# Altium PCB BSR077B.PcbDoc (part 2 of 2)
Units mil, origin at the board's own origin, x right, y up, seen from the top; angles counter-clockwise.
Board outline 2900 x 1600 mil, 4 copper layers (Top Layer, Signal Layer 1, Signal Layer 2, Bottom Layer), stack 40 mil thick; 58 components, 11 nets, 111 pads, 62 vias.
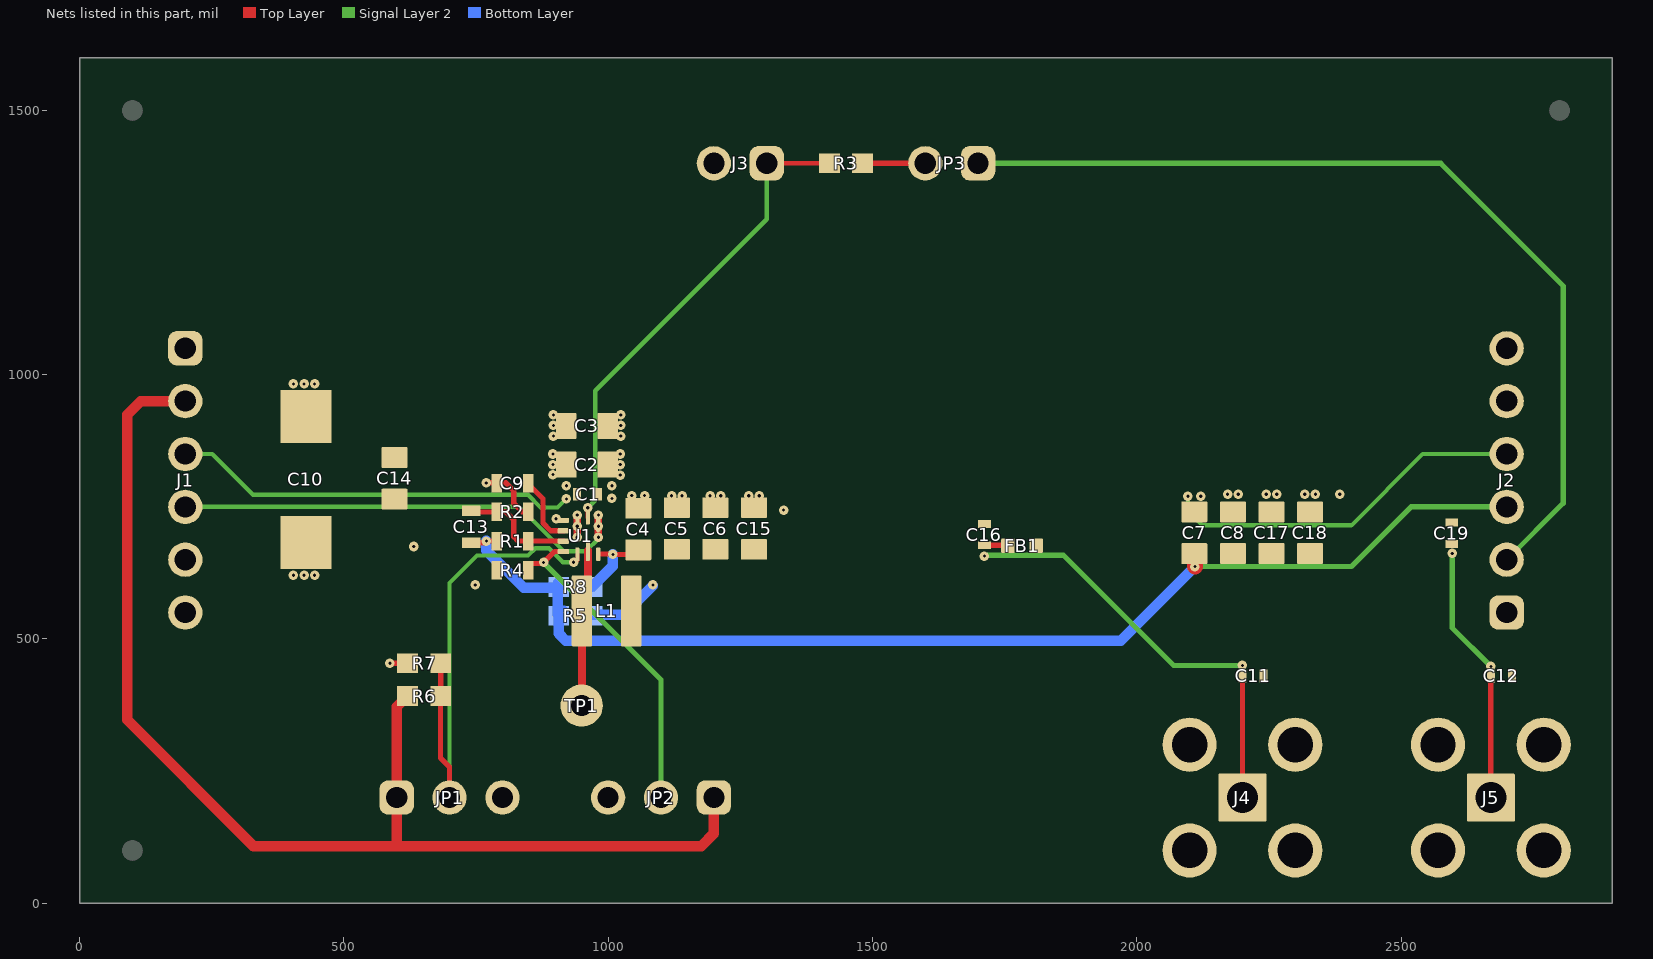
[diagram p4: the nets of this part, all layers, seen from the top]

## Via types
v1: diameter 18, hole 6, Top Layer to Bottom Layer, tented both sides, 53 vias
v2: diameter 18, hole 6.1, Top Layer to Bottom Layer, tented both sides, 9 vias

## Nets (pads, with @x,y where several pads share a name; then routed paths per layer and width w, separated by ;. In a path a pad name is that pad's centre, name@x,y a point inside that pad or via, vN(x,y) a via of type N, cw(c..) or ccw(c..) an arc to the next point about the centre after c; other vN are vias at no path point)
EN: JP1.2 R6.2 R7.2 U1.1 | length 992.7
  Top Layer w8: v2(934.59,645.35) 937.59,645.35 941.9,649.66 U1.1@941.9,660.45
  Top Layer w10: JP1.2@683,213 JP1.2@702,194 ; R7.2@683.5,454 R6.2@683.5,392 683,391.5 683,275 700,258 JP1.2@700,200
  Signal Layer 2 w8: JP1.2@700,200 700,606 752,658 848.35,658 862,671.65 887.9,671.65 914.2,645.35 v2(934.59,645.35) ; JP1.2@702,194 JP1.2@702,200
FB: C13.2 R1.1 R2.2 U1.9 | length 228.6
  Top Layer w10: C13.2@729.59,740.35 789,740.35 R2.2@791.59,740.35 ; R2.2@790.59,741.35 805.59,741.35 821.59,725.35 821.59,693.41 829.65,685.35 851.59,685.35 U1.9@915.33,685.06
GND: C1.2 C2.1 C3.1 C4.2 C5.2 C6.2 C7.2 C8.2 C9.2 C10.2 C11.2 C12.2 C14.1 C15.2 C16.2 C17.2 C18.2 C19.2 J1.4 J1.5 J1.6 J2.4 J2.5 J2.6 J3.2 J4.2 J4.3 J4.4 J4.5 J5.2 J5.3 J5.4 J5.5 JP1.3 JP2.3 R2.1 R4.1 R7.1 U1.4 U1.7 | length 1719.6
  Top Layer w10: v1(587,454) R7.1@620.5,454 ; v1(769.35,795.35) C9.2@791.59,795.35 ; C9.2@792.59,795.35 806.59,795.35 821.59,780.35 821.59,756.35 837.59,740.35 R2.1@851.59,740.35
  Top Layer w15: U1.4@981.27,734.03 U1.4@981.27,722.46 981.27,692.66 v2(981.59,692.35)
  Signal Layer 2 w8: J1.4@200,750 832,750 915.78,666.22 958.22,666.22 981.59,689.59 v2(981.59,692.35) ; v1(2097,770) 2097,743 2125,715 2406,715 2541,850 J2.4@2700,850
  other v1: 748.59,602.35 404.65,620.59 424.65,620.59 444.65,620.59 632.15,675 1332,744 1007,766 2121,770 1044.7,771.2 1069,771.2 1119.9,771 1139.9,771 1192.9,771 1212.9,771 1265.9,771 1285.9,771 2172,774 2192,774 2245,774 2265,774 2318,774 2338,774 2384,774 1007,790 1023,810 1023,830 1023,850 1024,884 1024,904 1024,924
  other v2: 981.59,713.35 901.59,727.35 981.59,734.35
NetJP3_2: JP3.2 R3.2 | length 125
  Top Layer w10: R3.2@1475,1400 R3.2@1481.5,1400 JP3.2@1600,1400
PG: J3.1 R3.1 U1.5 | length 937.6
  Top Layer w8: U1.5@961.59,729.35 v2(961.59,748.35) ; J3.1@1300,1400 R3.1@1418.5,1400 R3.1@1425,1400
  Signal Layer 2 w8: v2@963.35,748.35 v2(961.59,748.35) 975.62,762.38 975.62,969.62 1300,1294 J3.1@1300,1400
SCONF: JP2.2 R4.2 U1.10 | length 605.5
  Top Layer w10: R4.2@856,643 876,643 v1(878,645) 898.37,665.37 U1.10@915.33,665.37
  Signal Layer 2 w10: v1(878,645) 1100,423 JP2.2@1100,200
SS: C9.1 U1.8 | length 131.1
  Top Layer w10: C9.1@851.59,795.35 851.59,790.35 876.59,765.35 876.59,719.35 891.19,704.74 U1.8@915.33,704.74
SW: L1.1 TP1.1 U1.2 | length 294.9
  Top Layer w15: L1.1@948,541 L1.1@949,542 ; TP1.1@950,374 950.35,374.35 L1.1@950.35,553 ; L1.1@961.59,553 U1.2@961.59,667.34
VIN: C1.1 C2.2 C3.2 C10.1 C14.2 J1.1 J1.2 J1.3 JP1.1 JP2.1 R6.1 U1.6 | length 3102.8
  Top Layer w15: v2(941.59,692.35) v2(941.59,734.35)
  Top Layer w20: J1.2@200,950 116,950 90,924 90,347 329,108 599,108 ; JP1.1@602,194 JP1.1@611,203 ; R6.1@620.5,392 600,371.5 JP1.1@600,200 600,109 599,108 ; JP2.1@1200,200 1200,132 1176,108 599,108
  Signal Layer 2 w8: J1.3@200,850 251,850 328.13,772.87 848.13,772.87 872,749 904.24,749 920.24,765 v1(921,765) v1@922,765
  other v1: 921,790 895.42,811 895.42,830 895.42,850 896.42,884 896.42,904 896.42,924 404.65,982.59 424.65,982.59 444.65,982.59
  other v2: 941.59,713.35
VOUT: C4.1 C5.1 C6.1 C11.1 C15.1 C16.1 FB1.1 J4.1 L1.2 R5.2 R8.1 U1.3 | length 1161.5
  Top Layer w10: U1.3@983,661 1010,661 v1(1009,660) C4.1@1050,660 ; C16.1@1712,677.29 1755.43,677.29 FB1.1@1756.43,676.29 ; J4.1@2200,200 C11.1@2200,430 v1(2200,450)
  Signal Layer 2 w10: v1(1712,656.75) 1713.71,658.46 1861.54,658.46 2070,450 v1(2200,450)
  Bottom Layer w10: R5.2@967.5,546 R5.2@969.5,548 ; v1@1084.6,600.6 v1(1084.6,602.35)
  Bottom Layer w20: R5.2@967.5,546 1030,546 v1@1084.6,600.6 ; R8.1@969.5,598.5 1009,638 v1(1009,660)
VOUT_FILT: C7.1 C8.1 C12.1 C13.1 C17.1 C18.1 C19.1 FB1.2 J2.1 J2.2 J2.3 J5.1 JP3.1 R1.2 R5.1 R8.2 | length 4560.9
  Top Layer w10: C13.1@740.59,682.35 766.59,682.35 v1(769.59,685.35) R1.2@791.59,685.35 ; J5.1@2670,200 C12.1@2670,430 v1(2670,448) ; J2.1@2700,551 J2.1@2705,546
  Top Layer w30: C7.1@2109,661.63 2110,660.63 v1(2110,637)
  Signal Layer 2 w10: JP3.1@1700,1400 2575,1400 2807,1168 2807,757 J2.2@2700,650 ; v1(2110,637) 2406.25,637 2519.25,750 J2.3@2700,750 ; v1(2597,662) 2597,521 v1(2670,448)
  Bottom Layer w10: R8.2@896.5,597 904.5,605 915,605 R8.2@915.26,598.88 ; R5.1@906.5,544 904.5,546 R5.1@917,558.5
  Bottom Layer w20: v1(769.59,685.35) 769.59,667.41 840,597 R8.2@896.5,597 ; R5.1@904.5,546 R8.2@904.5,605 ; R5.1@906.5,544 906.5,510.5 920,497 1970,497 v1(2110,637)
pads on no net: FID1.1 FID2.1 FID3.1 FID4.1 FID5.1 FID6.1 LBL1.0 SH-JP1.0 SH-JP2.0 SH-JP3.0

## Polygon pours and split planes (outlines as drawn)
GND on Bottom Layer "BOTTOM_LAYER_GND_P084" (solid, remove dead copper, pour order 84): 0,1600 2900,1600 2900,0 0,0
VOUT on Top Layer "TOP_LAYER_VOUT_P090" (solid, remove dead copper, pour order 90): 1344,480 1773,480 1773,693.96 1030,694.03 1030,620 1010,620 1000,610 1000,479.89 1229,479.89 1229,480
GND on Top Layer "TOP_LAYER_GND_P096" (solid, remove dead copper, pour order 96): 0,1600 2900,1600 2900,0 0,0
VOUT_FILT on Top Layer "TOP_LAYER_VOUT_FILT_P094" (solid, remove dead copper, pour order 94): 1783,480 2118,480 2720,480 2750,510 2750,694.17 1783,694.17 1783,644
VIN on Top Layer "TOP_LAYER_VIN_P086" (solid, remove dead copper, pour order 86): 930,680 930,720.71 826.77,823 130,823 130,1120 853,1120 955,1018 955,680
GND on Signal Layer 1 "SIGNAL_LAYER_1_GND_P078" (solid, remove dead copper, pour order 78): 0,1600 2900,1600 2900,0 0,0
GND on Signal Layer 2 "SIGNAL_LAYER_2_GND_P098" (solid, remove dead copper, pour order 98): -0.1,1597.05 2899.9,1597.05 2899.9,-2.95 -0.1,-2.95
VIN on Signal Layer 2 "SIGNAL_LAYER_2_VIN_P080" (solid, remove dead copper, pour order 80): 930,680 930,731.05 872.53,788 335,788 223.47,899.53 130,899.53 130,1118 853,1118 960,1011 960,680

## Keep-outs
Keep-Out Layer:
  text ".Layer_Name" at 577,-858.49 h60

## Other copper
Top Layer:
  pour cut-out: 2699.88,890.06 cw(c2699.88,849.64) 2740.3,849.64 cw(c2699.88,849.64) 2699.88,809.22 cw(c2699.88,849.64) 2659.47,849.64 cw(c2699.88,849.64)
  pour cut-out: 199.88,890.06 cw(c199.88,849.64) 240.3,849.64 cw(c199.88,849.64) 199.88,809.22 cw(c199.88,849.64) 159.47,849.64 cw(c199.88,849.64)
  pour cut-out: 199.88,790.06 cw(c199.88,749.64) 240.3,749.64 cw(c199.88,749.64) 199.88,709.22 cw(c199.88,749.64) 159.47,749.64 cw(c199.88,749.64)
  pour cut-out: 1391.59,352.35
  pour cut-out: 2450,499.46
  pour cut-out: 1450,534
  text ".Layer_Name" at 577,-858.49 h60
Signal Layer 1:
  pour cut-out: 2699.82,809.73 cw(c2699.82,850.14) 2659.4,850.14 cw(c2699.82,850.14) 2699.82,890.56 cw(c2699.82,850.14) 2740.23,850.14 cw(c2699.82,850.14)
  pour cut-out: 199.82,709.73 cw(c199.82,750.14) 159.4,750.14 cw(c199.82,750.14) 199.82,790.56 cw(c199.82,750.14) 240.23,750.14 cw(c199.82,750.14)
  pour cut-out: 967.9,691.9 ccw(c981.9,691.9) 981.9,677.9 ccw(c981.9,691.9) 995.9,691.9 ccw(c981.9,691.9) 981.9,705.9 ccw(c981.9,691.9)
  pour cut-out: 199.82,809.73 cw(c199.82,850.14) 159.4,850.14 cw(c199.82,850.14) 199.82,890.56 cw(c199.82,850.14) 240.23,850.14 cw(c199.82,850.14)
  pour cut-out: 1421,898
  text ".Layer_Name" at 577,-858.49 h60
Signal Layer 2:
  pour cut-out: 2699.64,809.47 cw(c2699.64,849.88) 2659.22,849.88 cw(c2699.64,849.88) 2699.64,890.3 cw(c2699.64,849.88) 2740.06,849.88 cw(c2699.64,849.88)
  pour cut-out: 199.64,709.47 cw(c199.64,749.88) 159.22,749.88 cw(c199.64,749.88) 199.64,790.3 cw(c199.64,749.88) 240.06,749.88 cw(c199.64,749.88)
  pour cut-out: 2083.39,770 ccw(c2097.39,770) 2097.39,756 ccw(c2097.39,770) 2111.39,770 ccw(c2097.39,770) 2097.39,784 ccw(c2097.39,770)
  pour cut-out: 199.64,809.47 cw(c199.64,849.88) 159.22,849.88 cw(c199.64,849.88) 199.64,890.3 cw(c199.64,849.88) 240.06,849.88 cw(c199.64,849.88)
  pour cut-out: 2701,836 2547,836 2412,701 2118,701 2083,736 2083,769 2087,773 2111,773 2111,751 2133,729 2399,729 2534,864 2694,864
  pour cut-out: 839.94,761.68 270.06,761.68 200,761.68 200,738 283,738 828.49,738 862,704 910,656 970.2,656 988,673.8 988,697 971.21,697 953.5,678.5 925.5,678.5 886.31,715.31
  text ".Layer_Name" at 577,-858.49 h60
Bottom Layer:
  pour cut-out: 2700.12,810 cw(c2700.12,850.42) 2659.7,850.42 cw(c2700.12,850.42) 2700.12,890.83 cw(c2700.12,850.42) 2740.53,850.42 cw(c2700.12,850.42)
  pour cut-out: 1031.02,770.75 ccw(c1045.02,770.75) 1045.02,756.75 ccw(c1045.02,770.75) 1059.02,770.75 ccw(c1045.02,770.75) 1045.02,784.75 ccw(c1045.02,770.75)
  pour cut-out: 200.12,710 cw(c200.12,750.42) 159.7,750.42 cw(c200.12,750.42) 200.12,790.83 cw(c200.12,750.42) 240.53,750.42 cw(c200.12,750.42)
  pour cut-out: 2699.58,709.59 cw(c2699.58,750.01) 2659.17,750.01 cw(c2699.58,750.01) 2699.58,790.43 cw(c2699.58,750.01) 2740,750.01 cw(c2699.58,750.01)
  pour cut-out: 200.12,810 cw(c200.12,850.42) 159.7,850.42 cw(c200.12,850.42) 200.12,890.83 cw(c200.12,850.42) 240.53,850.42 cw(c200.12,850.42)
  pour cut-out: 684.85,686
  pour cut-out: 676.5,684.5
  text ".Layer_Name" at 577,-858.49 h60

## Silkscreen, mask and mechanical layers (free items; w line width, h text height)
Top Overlay:
  text "GND" at 1130,1274 h35
  text "PG" at 1278,1274 h35
  text "'.PRJ_Number'" at 1919,1087 h40
  text "GND" at 2526,1032 h35
  text "REV..PCB_Rev" at 1920,1014 h40
  text "VIN" at 260,980 h35
  text "S+" at 265,832 h35
  text "S-" at 2544,828 h35
  text "S+" at 2543,735 h35
  text "S-" at 265,733 h35
  text "GND" at 258,588 h35
  text "VOUT_FILT" at 2339,534 h35
  text "SW" at 802,417 h35
  text "VOUT_FILT" at 2518,367 h35
  text "VOUT" at 2135.49,366 h35
  text "EN/SYNC" at 589.75,309 h35
  text "S-CONF" at 1019.8,309 h35
  text "OFF" at 760,259 h35
  text "1MHz" at 934,259 h35
  text "ON" at 567,258 h35
  text "2.2MHz" at 1139,258 h35
  text ".Layer_Name" at 577,-858.49 h60
Bottom Overlay:
  text ".Layer_Name" at 577,-858.49 h60
Top Paste:
  text ".Layer_Name" at 577,-858.49 h60
Bottom Paste:
  text ".Layer_Name" at 577,-858.49 h60
Top Solder:
  text ".Layer_Name" at 577,-858.49 h60
  text ".Layer_Name" at 577,-858.49 h60
Bottom Solder:
  text ".Layer_Name" at 577,-858.49 h60
Drill Guide:
  text ".Layer_Name" at 577,-858.49 h60
M1 Board Outline:
  the board outline again, w10
  text ".Layer_Name" at 577,-858.49 h60
M2 Board Dimensions:
  rectangle: 0,-275 125,-150
  rectangle: 125,-400 500,-275
  lines w7: 0,-275 1000,-275 ; 125,-400 125,-150 ; 250,-400 250,-150 ; 500,-400 500,-150 ; 750,-400 750,-150 ; 0,-400 1000,-400 1000,-150 0,-150 0,-400
  text ".Layer_Name" at 577,-858.49 h60
M3 3D STEP Top:
  text ".Layer_Name" at 577,-858.49 h60
M4 3D STEP Bottom:
  text ".Layer_Name" at 577,-858.49 h60
M5 Assembly Top:
  lines w10: -292,-930.17 6308,-930.17 ; -292,-726.83 6310,-726.83 ; -292,-523.5 -292,-1133.5 3713,-1133.5 6310,-1133.5 6310,-523.5 -291.5,-523.5 -291.5,-1133.5 1284,-1133.5 ; 2173,-1133.5 2173,-523.5 ; 3440,-726.83 3440,-523.5 ; 4280,-726.83 4280,-523.5 ; 4902,-1140 4902,-937.17
  text "COMPONENTS MARKED 'DNP' SHOULD NOT BE POPULATED." at 1153.5,-318.5 h60
  text "ASSEMBLY VARIANT:" at 1153,-434 h60
  text ".VariantName" at 2189,-434 h60
  text "PCB VIEWED FROM TOP SIDE" at -228.5,-655.67 h60
  text "BOARD #:" at 2248,-655.67 h60
  text ".PRJ_Number" at 2793.5,-655.67 h60
  text "REV:" at 3638,-655.67 h60
  text ".PCB_Rev" at 3929.5,-655.67 h60
  text "SVN REV:" at 4476,-655.67 h60
  text ".VersionControl_RevNumber" at 4982,-655.67 h60
  text "TID #:" at 2248,-859 h60
  text ".TID" at 2793.5,-859 h60
  text "PLOT NAME =" at -228.5,-1064.34 h60
  text ".plot_File_Name" at 577,-1064.34 h60
  text "GENERATED    :" at 2250,-1064.34 h60
  text ".Print_Date" at 3119.5,-1064.34 h60
  text ".Print_Time" at 3848.5,-1064.34 h60
  text "TEXAS INSTRUMENTS" at 5113,-1064.34 h60
M6 Assembly Bottom:
  lines w10: -292.5,-727.33 6309.5,-727.33 ; -290.5,-930.67 6309.5,-930.67 ; 1115.5,-1140.5 1115.5,-937.67 ; 1737.5,-727.33 1737.5,-524 ; 2577.5,-727.33 2577.5,-524 ; 3844.5,-1134 3844.5,-524 ; 4733.5,-1134 6309,-1134 6309,-524 -292.5,-524 -292.5,-1134 2304.5,-1134 6309.5,-1134 6309.5,-524
  text "COMPONENTS MARKED 'DNP' SHOULD NOT BE POPULATED." at 6102,-318 h60
  text ".VariantName" at 5058,-434 h60
  text "ASSEMBLY VARIANT:" at 6097,-434 h60
  text ".VersionControl_RevNumber" at 1035.5,-656.17 h60
  text "SVN REV:" at 1541.5,-656.17 h60
  text ".PCB_Rev" at 2088,-656.17 h60
  text "REV:" at 2379.5,-656.17 h60
  text ".PRJ_Number" at 3224,-656.17 h60
  text "BOARD #:" at 3769.5,-656.17 h60
  text "PCB VIEWED FROM BOTTOM SIDE" at 6246,-656.17 h60
  text ".TID" at 3224,-859.5 h60
  text "TID #:" at 3769.5,-859.5 h60
  text "TEXAS INSTRUMENTS" at 904.5,-1064.84 h60
  text ".Print_Time" at 2169,-1064.84 h60
  text ".Print_Date" at 2898,-1064.84 h60
  text "GENERATED    :" at 3767.5,-1064.84 h60
  text ".plot_File_Name" at 5440.5,-1064.84 h60
  text "PLOT NAME =" at 6246,-1064.84 h60
M9 Title Sheet:
  drawing of 57 lines, arcs and shapes, not listed
  text "1" at 739.84,8036.5 h70
  text "2" at 3235.5,8036.5 h70
  text "3" at 5724.84,8036.5 h70
  text "4" at 8231.51,8036.5 h70
  text "5" at 10730.5,8036.5 h70
  text "6" at 13235.5,8036.5 h70
  text "A" at -416.5,6893.5 h70
  text "A" at 14383.5,6893.5 h70
  text "B" at -416.5,4513.5 h70
  text "B" at 14383.5,4513.5 h70
  text "C" at -416.5,2138.5 h70
  text "C" at 14383.5,2138.5 h70
  text "PROJECT TITLE:" at 11343.5,277.5 h45
  text ".PRJ_Title" at 11393.5,144.17 h70
  text "DESIGNED FOR:" at 11343.5,-23.5 h45
  text ".PRJ_Customer" at 11393.5,-163.5 h70
  text "D" at -416.5,-231.5 h70
  text "D" at 14383.5,-231.5 h70
  text "FILE NAME:" at 11343.5,-323.5 h45
  text ".PCB_File_Name_No_Path" at 11393.5,-443.5 h70
  text "Texas Instruments (TI) and/or its licensors do not warrant the accuracy or completeness of this specification" at 6374,-605.34 h45
  text "ENGINEER:" at 11343.5,-613.5 h45
  text "LAYOUT BY:" at 12848.5,-613.5 h45
  text "or any information contained therein. TI and/or its licensors do not warrant that this design will meet" at 6329.01,-718 h45
  text ".PRJ_Engineer" at 11393.5,-768.49 h70
  text ".PCB_Layout" at 12899,-768.49 h70
  text "the specifications, will be suitable for your application or fit for any particular purpose, or will operate in" at 6329.01,-830.67 h45
  text ".Layer_Name" at 577,-858.49 h60
  text "ALTIUM DESIGNER VERSION:" at 12848.5,-923.5 h45
  text "an implementation. TI and/or its licensors do not warrant that the design is production worthy. You should" at 6329.01,-943.33 h45
  text "completely validate and test your design implementation to confirm the system functionality for your application." at 6374,-1056 h45
  text ".print_Scale" at 11393.5,-1056.83 h70
  text ".Application_BuildNumber" at 12899,-1056.83 h70
  text "1" at 739.84,-1263.5 h70
  text "2" at 3235.5,-1263.5 h70
  text "3" at 5724.84,-1263.5 h70
  text "4" at 8231.51,-1263.5 h70
  text "5" at 10730.5,-1263.5 h70
  text "6" at 13235.5,-1263.5 h70
M10 Fab Notes:
  drawing of 189 lines, arcs and shapes, not listed
  text "DESIGN INFORMATION" at 12381.52,6356.17 h60
  text "MIN. TRACK WIDTH:" at 11736.96,6224.05 h60
  text "8" at 12833.2,6224.05 h60
  text "MIL" at 12987.96,6224.05 h60
  text "5.9" at 12777,6105 h60
  text "MIN. CLEARANCE:" at 11736.96,6099.92 h60
  text "MIL" at 12987.96,6099.92 h60
  text "MIN. VIA PAD SIZE:" at 11736.96,5975.8 h60
  text "18" at 12803.21,5975.8 h60
  text "MIL" at 12987.96,5975.8 h60
  text "0.05mm (2MIL)" at 12431.96,5845.9 h60
  text "MINIMUM ANNULAR RING" at 11407.73,5837.67 h60
  text "EXTERNAL" at 13139.96,5837.67 h60
  text "PER" at 11607.73,5727.55 h60
  text "IPC-D-275 CLASS 2 LEVEL C" at 11827.73,5727.54 h60
  text "MIL, HOLES" at 13315.96,5627.07 h60
  text "+/-" at 12923.5,5618.48 h60
  text "+/-" at 13777.5,5618.48 h60
  text "REGISTRATION TOLERANCES:" at 11407.73,5617.42 h60
  text "METAL" at 12607.5,5617.42 h60
  text "5" at 13183.7,5617.42 h60
  text "3" at 14016.7,5617.42 h60
  text "MIL" at 14132.96,5617.42 h60
  text "HOLE SIZE TOLERANCE (UNLESS OTHERWISE SPECIFIED):" at 11407.73,5519.1 h60
  text "+/-" at 13777.5,5516.23 h60
  text "3" at 14016.7,5515.17 h60
  text "MIL" at 14132.96,5515.17 h60
  text "MATERIAL:" at 11332.96,5377.52 h60
  text "FR-4 High Tg" at 12319.4,5249 h60
  text "X" at 12174.96,5241.01 h60
  text "FR-408" at 11753.96,5236.49 h60
  text "OTHER" at 13241.96,5236.49 h60
  text "40 MIL (1.0mm) +/-10%" at 12074.06,5093.46 h60
  text "X" at 11953.96,5091.01 h60
  text "THICKNESS:" at 11407.73,5085.24 h60
  text "OTHER" at 13358.96,5085.24 h60
  text "TOLERANCE:" at 11407.73,4946.92 h60
  text "X" at 12255.96,4946.92 h60
  text "ANSI IPC-6012 TYPE 3 CLASS 2" at 12433.98,4946.92 h60
  text "OTHER +/-" at 12433.96,4802.73 h60
  text "BOW & TWIST:" at 11407.73,4657.54 h60
  text "X" at 12255.96,4657.54 h60
  text "ANSI IPC-6012 TYPE 3 CLASS 2" at 12433.98,4657.54 h60
  text "OTHER +/-" at 12433.96,4510.85 h60
  text "DRILLING:" at 11332.96,4380.23 h60
  text "NC_DRILL FILES" at 13093.96,4275.04 h60
  text "REFERENCE:" at 11407.73,4271.1 h60
  text "X" at 12064.96,4271.01 h60
  text "AS SHOWN" at 12242.96,4271.1 h60
  text "X" at 12965.96,4271.1 h60
  text "OTHER" at 13391.96,4128.85 h60
  text "PTH COPPER THICKNESS:" at 11407.41,4125.32 h60
  text "X" at 12546.64,4125.32 h60
  text "20-30 um" at 12674.64,4125.32 h60
  text "BOARD FINISH:" at 11332.96,3977.73 h60
  text "SILKSCREEN:" at 11488.18,3867.6 h60
  text "X" at 12445.96,3867.6 h60
  text "TOP" at 12562.96,3867.6 h60
  text "X" at 12955.96,3867.6 h60
  text "BOTTOM" at 13073.96,3867.6 h60
  text "SILKSCREEN COLOR:" at 11488.18,3712.41 h60
  text "X" at 12444.96,3712.41 h60
  text "WHITE" at 12562.96,3712.41 h60
  text "OTHER" at 13073.96,3712.41 h60
  text "X" at 12575.96,3568.96 h60
  text "GREEN" at 12693.96,3568.96 h60
  text "OTHER" at 13311.96,3568.96 h60
  text "SOLDER RESIST COLOR:" at 11488.18,3562.1 h60
  text "X" at 12575.96,3414.71 h60
  text "MATTE" at 12693.96,3414.71 h60
  text "SEMI-GLOSS" at 13311.5,3414.07 h60
  text "IMMERSION GOLD (ENIG)" at 12393.96,3241.94 h60
  text "ENEPIG" at 13731.5,3234.72 h60
  text "SURFACE FINISH:" at 11332.96,3233.72 h60
  text "X" at 12215.96,3233.72 h60
  text "IMM. TIN/SILVER OR EQUIV" at 11662.5,3096.4 h60
  text "OTHER" at 13093.96,3092.47 h60
  text "ARRAY/PANEL:" at 11332.96,2937.09 h60
  text "CUT AND TRIM PER M1 BOARD OUTLINE" at 12393.96,2928.87 h60
  text "N.C. ROUTE" at 12393.96,2792.9 h60
  text "X" at 13081.96,2792.9 h60
  text "V. SCORE" at 13259.96,2792.9 h60
  text "CERTIFICATION:" at 11332.96,2663.77 h60
  text "MATERIALS AND WORKMANSHIP FOR ALL PCBS" at 12057.96,2663.77 h60
  text "TO MEET OR EXCEED THE REQUIREMENTS OF:" at 12057.96,2569.71 h60
  text "X" at 11695.47,2441.08 h60
  text "ANSI IPC-A-600F CLASS ->" at 11823.46,2441.08 h60
  text "X" at 13471.47,2441.08 h60
  text "2" at 13581.46,2441.08 h60
  text "1" at 13266.46,2439.58 h60
  text "3" at 13935.46,2439.58 h60
  text "X" at 12507.47,2293.39 h60
  text "RoHS" at 12635.46,2293.39 h60
  text "OTHER" at 13279.86,2293.39 h60
  text "PER ORDER" at 13676.92,2293.39 h60
  text "ALL BOARDS MUST MEET OR EXCEED UL94-V0 REQUIREMENTS." at 11360.5,2139.57 h60
  text "PCB MUST BEAR THE UL94V-0 UL REGISTERED MATERIAL ID NUMBER" at 11360.5,2023.5 h60
  text "ADDITIONAL REQUIREMENTS:" at 11332.96,1854.08 h60
  text "MICROSECTION:" at 11407.73,1746.95 h60
  text "YES" at 12313.46,1746.95 h60
  text "REQUIRED" at 13174.96,1602.62 h60
  text "BARE BOARD ELEC. TEST:" at 11407.73,1599.76 h60
  text "NONE" at 12713.46,1599.76 h60
  text "X" at 13056.96,1599.76 h60
  text "PER ORDER" at 13766.96,1599.76 h60
  text "X" at 11465.47,1449.39 h60
  text "6.1MIL VIAS REQUIRE NON-CONDUCTIVE FILL AND PLANARIZE" at 11575.88,1394.82 h59
  text "XX MIL VIAS REQUIRE CONDUCTIVE FILL AND PLANARIZE" at 11583.88,1290.84 h60
  text "OUTER XX MIL TRACES REQUIRE 50 OHM SINGLE-ENDED IMPEDANCE" at 11582.89,1127.46 h58
  text "LAYER 2 & 3 (INNER LAYERS) XX MIL WIDE, XX MIL SPACE / TRACES REQUIRE 100 OHM DIFFERENTIAL IMPEDANCE" at 11574.89,891.74 h60
  text ".Layer_Name" at 577,-858.49 h60
M11 Gerber Information:
  lines w10: -292,-930.17 6308,-930.17 ; -292,-726.83 6310,-726.83 ; -292,-523.5 -292,-1133.5 3713,-1133.5 6310,-1133.5 6310,-523.5 -291.5,-523.5 -291.5,-1133.5 1284,-1133.5 ; 2173,-1133.5 2173,-523.5 ; 3440,-726.83 3440,-523.5 ; 4280,-726.83 4280,-523.5 ; 4902,-1140 4902,-937.17
  text "ALL ARTWORK VIEWED FROM TOP SIDE" at -228.5,-655.67 h60
  text "BOARD #:" at 2248,-655.67 h60
  text ".PRJ_Number" at 2793.5,-655.67 h60
  text "REV:" at 3638,-655.67 h60
  text ".PCB_Rev" at 3929.5,-655.67 h60
  text "SVN REV:" at 4476,-655.67 h60
  text ".VersionControl_RevNumber" at 4982,-655.67 h60
  text "LAYER NAME =" at -228.5,-858.49 h60
  text "TID #:" at 2248,-859 h60
  text ".TID" at 2793.5,-859 h60
  text "PLOT NAME =" at -228.5,-1064.34 h60
  text ".plot_File_Name" at 577,-1064.34 h60
  text "GENERATED    :" at 2250,-1064.34 h60
  text ".Print_Date" at 3119.5,-1064.34 h60
  text ".Print_Time" at 3848.5,-1064.34 h60
  text "TEXAS INSTRUMENTS" at 5113,-1064.34 h60
M12 Stackup:
  drawing of 295 lines, arcs and shapes, not listed
  text "Layer" at 9808.58,7726.5 h60
  text "Name" at 10218.49,7726.5 h60
  text "Material" at 11158.23,7726.5 h60
  text "Thickness" at 12018,7726.5 h60
  text "Constant" at 12667.84,7726.5 h60
  text "Board Layer Stack" at 13237.7,7726.5 h60
  text "1" at 9808.58,7606.5 h60
  text "Top Overlay" at 10218.49,7606.5 h60
  text "2" at 9808.58,7486.5 h60
  text "Top Solder" at 10218.49,7486.5 h60
  text "Solder Resist" at 11158.23,7486.5 h60
  text "0.40mil" at 12018,7486.5 h60
  text "3.5" at 12667.84,7486.5 h60
  text "3" at 9808.58,7366.5 h60
  text "Top Layer" at 10218.49,7366.5 h60
  text "Copper" at 11158.23,7366.5 h60
  text "1.40mil" at 12018,7366.5 h60
  text "4" at 9808.58,7246.5 h60
  text "Dielectric 1" at 10218.49,7246.5 h60
  text "FR-4 High Tg" at 11158.23,7246.5 h60
  text "5.00mil" at 12018,7246.5 h60
  text "4.2" at 12667.84,7246.5 h60
  text "5" at 9808.58,7126.5 h60
  text "Signal Layer 1" at 10218.49,7126.5 h60
  text "Copper" at 11158.23,7126.5 h60
  text "1.40mil" at 12018,7126.5 h60
  text "6" at 9808.58,7006.5 h60
  text "Dielectric 2" at 10218.49,7006.5 h60
  text "FR-4 High Tg" at 11158.23,7006.5 h60
  text "24.40mil" at 12018,7006.5 h60
  text "4.2" at 12667.84,7006.5 h60
  text "7" at 9808.58,6886.5 h60
  text "Signal Layer 2" at 10218.49,6886.5 h60
  text "Copper" at 11158.23,6886.5 h60
  text "1.40mil" at 12018,6886.5 h60
  text "8" at 9808.58,6766.5 h60
  text "Dielectric 3" at 10218.49,6766.5 h60
  text "FR-4 High Tg" at 11158.23,6766.5 h60
  text "5.00mil" at 12018,6766.5 h60
  text "4.2" at 12667.84,6766.5 h60
  text "9" at 9808.58,6646.5 h60
  text "Bottom Layer" at 10218.49,6646.5 h60
  text "Copper" at 11158.23,6646.5 h60
  text "1.40mil" at 12018,6646.5 h60
  text "10" at 9808.58,6526.5 h60
  text "Bottom Solder" at 10218.49,6526.5 h60
  text "Solder Resist" at 11158.23,6526.5 h60
  text "0.40mil" at 12018,6526.5 h60
  text "3.5" at 12667.84,6526.5 h60
  text "11" at 9808.58,6406.5 h60
  text "Bottom Overlay" at 10218.49,6406.5 h60
  text ".Layer_Name" at 577,-858.49 h60
M13 Component Bodies Top:
  text ".Layer_Name" at 577,-858.49 h60
M14 Component Bodies Bottom:
  text ".Layer_Name" at 577,-858.49 h60
M15 Courtyards Top:
  text ".Layer_Name" at 577,-858.49 h60
M16 Courtyards Bottom:
  text ".Layer_Name" at 577,-858.49 h60
Drill Drawing:
  circle w10: c3110.63,1397.32 r27.59
  lines w10: 3083.04,1010.99 3096.83,1010.99 3096.83,997.2 3124.43,997.2 3124.43,1010.99 3138.23,1010.99 3138.23,1038.59 3124.43,1038.59 3124.43,1052.39 3096.83,1052.39 3096.83,1038.59 3083.04,1038.59 3083.04,1010.99 ; 3083.04,1121.37 3110.63,1135.17 3138.23,1121.37 3124.43,1148.97 3138.23,1176.56 3110.63,1162.76 3083.04,1176.56 3096.83,1148.97 3083.04,1121.37 ; 3083.04,1245.55 3138.23,1245.55 3138.23,1300.74 3083.04,1300.74 3083.04,1245.55 ; 3083.04,1493.9 3083.04,1507.7 3096.83,1521.49 3083.04,1535.29 3083.04,1549.09 3096.83,1549.09 3110.63,1535.29 3124.43,1549.09 3138.23,1549.09 3138.23,1535.29 3124.43,1521.49 3138.23,1507.7 3138.23,1493.9 3124.43,1493.9 3110.63,1507.7 3096.83,1493.9 3083.04,1493.9
  lines w12: 3033,959.94 6263.52,959.94 ; 3033,1580.82 6263.52,1580.82 ; 3370.86,835.77 3370.86,1705 ; 3702.86,835.77 3702.86,1705 ; 4339.42,835.77 4339.42,1705 ; 4598.53,835.77 4598.53,1705 ; 4973.68,835.77 4973.68,1705 ; 5697.06,835.77 5697.06,1705 ; 3033,835.77 6263.52,835.77 6263.52,1705 3033,1705 3033,835.77
  text "Symbol" at 3107.51,1618.08 h72
  text "Quantity" at 3408.11,1618.08 h72
  text "Finished Hole Size" at 3740.12,1618.08 h72
  text "Plated" at 4376.67,1618.08 h72
  text "Hole Type" at 4635.78,1618.08 h72
  text "Drill Layer Pair" at 5010.93,1618.08 h72
  text "Hole Tolerance" at 5734.32,1618.08 h72
  text "53" at 3408.11,1493.9 h60
  text "0.152mm (6.00mil)" at 3740.12,1493.9 h60
  text "PTH" at 4376.67,1493.9 h60
  text "Round" at 4635.78,1493.9 h60
  text "Top Layer - Bottom Layer" at 5010.93,1493.9 h60
  text "9" at 3408.11,1369.72 h60
  text "0.155mm (6.10mil)" at 3740.12,1369.72 h60
  text "PTH" at 4376.67,1369.72 h60
  text "Round" at 4635.78,1369.72 h60
  text "Top Layer - Bottom Layer" at 5010.93,1369.72 h60
  text "23" at 3408.11,1245.55 h60
  text "1.016mm (40.00mil)" at 3740.12,1245.55 h60
  text "PTH" at 4376.67,1245.55 h60
  text "Round" at 4635.78,1245.55 h60
  text "Top Layer - Bottom Layer" at 5010.93,1245.55 h60
  text "2" at 3408.11,1121.37 h60
  text "1.500mm (59.06mil)" at 3740.12,1121.37 h60
  text "PTH" at 4376.67,1121.37 h60
  text "Round" at 4635.78,1121.37 h60
  text "Top Layer - Bottom Layer" at 5010.93,1121.37 h60
  text "8" at 3408.11,997.2 h60
  text "1.700mm (66.93mil)" at 3740.12,997.2 h60
  text "PTH" at 4376.67,997.2 h60
  text "Round" at 4635.78,997.2 h60
  text "Top Layer - Bottom Layer" at 5010.93,997.2 h60
  text "95 Total" at 3408.11,873.02 h60
Mechanical 17:
  text ".Layer_Name" at 577,-858.49 h60
Mechanical 18:
  text ".Layer_Name" at 577,-858.49 h60
Mechanical 19:
  text ".Layer_Name" at 577,-858.49 h60

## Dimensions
0,0 to 0,1600 on M2 Board Dimensions
0,-400 to 1000,-400 on M2 Board Dimensions
0,0 to 2900,0 on M2 Board Dimensions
